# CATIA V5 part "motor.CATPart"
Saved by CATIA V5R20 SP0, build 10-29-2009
Part number: motor
Bounding box of the stored display mesh (mm): x -4 to 25.121, y -3.36 to 16.146, z 0 to 2.4
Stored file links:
  C:\Users\user\OneDrive\바탕 화면\지혜 카티아\motor.CATPart
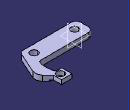
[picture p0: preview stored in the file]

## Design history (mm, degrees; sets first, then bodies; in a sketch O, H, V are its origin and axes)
Body1 (main body)
  Sketch1 on xy-plane, origin (0, 0, 0), H (1, 0, 0), V (0, 1, 0)
    circle A1 centre (0, 0) radius 1.665
    circle A2 centre (17.7, 0) radius 1.665
    point P1 (17.7, 0)
    line L1 (-2, 4.24) -> (19.365, 4.24)
    line L2 (19.1404, -3.36) -> (-2, -3.36)
    line L3 (-4, -1.36) -> (-4, 2.24)
    point P2 (19.365, 4.24)
    circle A3 centre (19.77, 13.65) radius 1.665
    point P3 (19.77, 13.65)
    construction line L4 (19.77, 16.2364) -> (19.77, -10.817)
    construction line L5 (8.4677, 13.65) -> (25.5, 13.65)
    line L6 (21.8655, 16.1462) -> (17.3321, 16.1462)
    line L7 (17.3321, 16.1462) -> (17.3321, 11.74)
    line L8 (17.3321, 11.74) -> (19.365, 11.74)
    point P11 (19.365, 11.74)
    line L9 (21.8655, 16.1462) -> (21.8655, 12.7727)
    line L10 (21.8655, 12.7727) -> (24.2721, 10.2236)
    line L11 (24.8848, 6.6357) -> (20.9678, -2.1726)
    axis line L12 (19.365, 11.74) -> (19.365, -2.3622)
    point P14 (19.365, 7.99)
    ellipse A4 centre (19.365, 7.99) semi-axes 3.75, 1.1908 rotation 270 from (19.365, 4.24) to (19.365, 11.74)
    point P15 (19.365, 11.74)
    point P16 (19.365, 4.24)
    arc A5 centre (21.8848, 7.9697) radius 3.2832 from (24.2721, 10.2236) to (24.8848, 6.6357) cw
    arc A6 centre (19.1404, -1.36) radius 2 from (19.1404, -3.36) to (20.9678, -2.1726) ccw
    arc A7 centre (-2, 2.24) radius 2 from (-2, 4.24) to (-4, 2.24) ccw
    arc A8 centre (-2, -1.36) radius 2 from (-2, -3.36) to (-4, -1.36) cw
    radius A1 = 1.665
    radius A2 = 1.665
    distance P1 O = 17.7
    distance P1 L1 = 4.24
    distance P1 L2 = 3.36
    distance L3 O = 4
    radius A3 = 1.665
    distance P1 L4 = 2.07
    distance L5 P1 = 13.65
    distance L8 L1 = 7.5
    radius A5 = 3.2832
    radius A6 = 2
    radius A7 = 2
    radius A8 = 2
    coincidence: P1 H, P3 L4, P3 L5, P11 L12, P2 L12, P14 L12, P11 A4, A4 P2, P2 P16, P11 P15
    horizontal: L1 H, L2 H, L5 H, L6 H, L8 H
    vertical: L3 V, L4 V, L7 V, L9 V, L12 V
    tangency: L12 A2, A5 L10, A5 L11, A6 L2, A6 L11, A7 L1, A7 L3, A8 L2, A8 L3
    parallelism: A4 L12
  Pad1: profile Sketch1, direction (0, 0, 1), length 2.4
  Sketch2 on face of Pad1 from Sketch1.L7, origin (17.3321, 0, 0), H (0, -1, 0), V (0, 0, 1)
    line L1 (-16.1462, 0.57) -> (-11.74, 0.57)
    line L2 (-11.74, 0.57) -> (-11.74, 0)
    line L3 (-11.74, 0) -> (-16.1462, 0)
    line L4 (-16.1462, 0) -> (-16.1462, 0.57)
    reference projected line E1 (-11.74, 0) -> (-11.74, 2.4) from edge [face of Pad1 from Sketch1.L8 | face of Pad1 from Sketch1.L7]
    reference projected line E2 (-16.1462, 0) -> (-16.1462, 2.4) from edge [face of Pad1 from Sketch1.L7 | face of Pad1 from Sketch1.L6]
    reference projected line E3 (-16.1462, 0) -> (-11.74, 0) from edge [start face of Pad1 | face of Pad1 from Sketch1.L7]
    length L4 = 0.57
    horizontal: L1 H, L3 H
    vertical: L2 V, L4 V
    coincidence: E1 L2, L4 E2, L3 E3
  Pocket1: profile Sketch2, direction (1, 0, 0), through (limit type 6)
